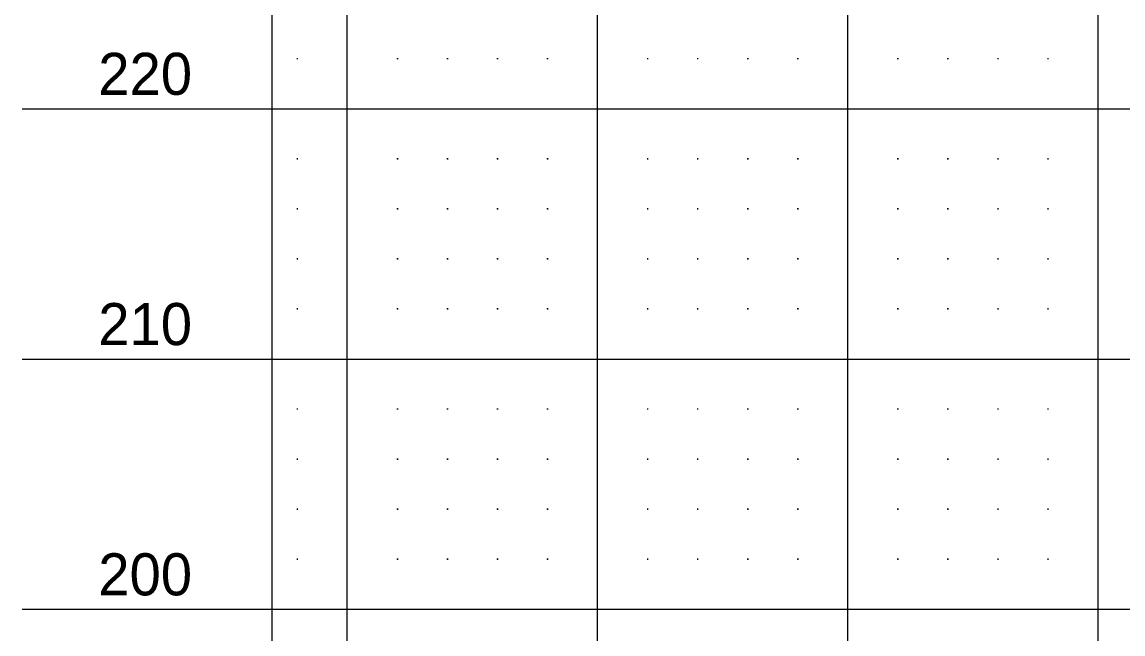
# Model space of a CAD drawing. Extents: x 471 to 2121, y 140 to 650.
# Drawn here: x 471.1 to 691, y 395.1 to 517.3 of the extents above; entities that cross this region are included whole.
import ezdxf

# ---------------------------------------------------------------- set-up
doc = ezdxf.new("R2010")
doc.units = 0
doc.layers.add('DSN_DRFT_Border Grid', color=7, linetype='Continuous')
doc.layers.add('DSN_RDWY_Prof Annotation', color=7, linetype='Continuous')

msp = doc.modelspace()

# ---------------------------------------------------------------- linework, layer by layer
at = {"layer": 'DSN_DRFT_Border Grid'}
for p, q in [((521.06, 150), (521.06, 650)), ((521.06, 150), (521.06, 650)), ((536.06, 150), (536.06, 650)), ((536.06, 150), (536.06, 650)), ((586.06, 150), (586.06, 650)), ((586.06, 150), (586.06, 650)), ((636.06, 150), (636.06, 650)), ((636.06, 150), (636.06, 650)), ((686.06, 150), (686.06, 650)), ((686.06, 150), (686.06, 650)), ((526.18, 510), (525.94, 510)), ((526.18, 510), (525.94, 510)), ((526.06, 510.12), (526.06, 509.88)), ((526.06, 510.12), (526.06, 509.88)), ((546.18, 510), (545.94, 510)), ((546.18, 510), (545.94, 510)), ((546.06, 510.12), (546.06, 509.88)), ((546.06, 510.12), (546.06, 509.88)), ((556.18, 510), (555.94, 510)), ((556.18, 510), (555.94, 510)), ((556.06, 510.12), (556.06, 509.88)), ((556.06, 510.12), (556.06, 509.88)), ((566.18, 510), (565.94, 510)), ((566.18, 510), (565.94, 510)), ((566.06, 510.12), (566.06, 509.88)), ((566.06, 510.12), (566.06, 509.88)), ((576.18, 510), (575.94, 510)), ((576.18, 510), (575.94, 510)), ((576.06, 510.12), (576.06, 509.88)), ((576.06, 510.12), (576.06, 509.88)), ((596.18, 510), (595.94, 510)), ((596.18, 510), (595.94, 510)), ((596.06, 510.12), (596.06, 509.88)), ((596.06, 510.12), (596.06, 509.88)), ((606.18, 510), (605.94, 510)), ((606.18, 510), (605.94, 510)), ((606.06, 510.12), (606.06, 509.88)), ((606.06, 510.12), (606.06, 509.88)), ((616.18, 510), (615.94, 510)), ((616.18, 510), (615.94, 510)), ((616.06, 510.12), (616.06, 509.88)), ((616.06, 510.12), (616.06, 509.88)), ((626.18, 510), (625.94, 510)), ((626.18, 510), (625.94, 510)), ((626.06, 510.12), (626.06, 509.88)), ((626.06, 510.12), (626.06, 509.88)), ((646.18, 510), (645.94, 510)), ((646.18, 510), (645.94, 510)), ((646.06, 510.12), (646.06, 509.88)), ((646.06, 510.12), (646.06, 509.88)), ((656.18, 510), (655.94, 510)), ((656.18, 510), (655.94, 510)), ((656.06, 510.12), (656.06, 509.88)), ((656.06, 510.12), (656.06, 509.88)), ((666.18, 510), (665.94, 510)), ((666.18, 510), (665.94, 510)), ((666.06, 510.12), (666.06, 509.88)), ((666.06, 510.12), (666.06, 509.88)), ((676.18, 510), (675.94, 510)), ((676.18, 510), (675.94, 510)), ((676.06, 510.12), (676.06, 509.88)), ((676.06, 510.12), (676.06, 509.88)), ((471.06, 500), (521.06, 500)), ((521.06, 500), (2071.06, 500)), ((521.06, 500), (2071.06, 500)), ((526.18, 490), (525.94, 490)), ((526.18, 490), (525.94, 490)), ((526.06, 490.12), (526.06, 489.88)), ((526.06, 490.12), (526.06, 489.88)), ((546.18, 490), (545.94, 490)), ((546.18, 490), (545.94, 490)), ((546.06, 490.12), (546.06, 489.88)), ((546.06, 490.12), (546.06, 489.88)), ((556.18, 490), (555.94, 490)), ((556.18, 490), (555.94, 490)), ((556.06, 490.12), (556.06, 489.88)), ((556.06, 490.12), (556.06, 489.88)), ((566.18, 490), (565.94, 490)), ((566.18, 490), (565.94, 490)), ((566.06, 490.12), (566.06, 489.88)), ((566.06, 490.12), (566.06, 489.88)), ((576.18, 490), (575.94, 490)), ((576.18, 490), (575.94, 490)), ((576.06, 490.12), (576.06, 489.88)), ((576.06, 490.12), (576.06, 489.88)), ((596.18, 490), (595.94, 490)), ((596.18, 490), (595.94, 490)), ((596.06, 490.12), (596.06, 489.88)), ((596.06, 490.12), (596.06, 489.88)), ((606.18, 490), (605.94, 490)), ((606.18, 490), (605.94, 490)), ((606.06, 490.12), (606.06, 489.88)), ((606.06, 490.12), (606.06, 489.88)), ((616.18, 490), (615.94, 490)), ((616.18, 490), (615.94, 490)), ((616.06, 490.12), (616.06, 489.88)), ((616.06, 490.12), (616.06, 489.88)), ((626.18, 490), (625.94, 490)), ((626.18, 490), (625.94, 490)), ((626.06, 490.12), (626.06, 489.88)), ((626.06, 490.12), (626.06, 489.88)), ((646.18, 490), (645.94, 490)), ((646.18, 490), (645.94, 490)), ((646.06, 490.12), (646.06, 489.88)), ((646.06, 490.12), (646.06, 489.88)), ((656.18, 490), (655.94, 490)), ((656.18, 490), (655.94, 490)), ((656.06, 490.12), (656.06, 489.88)), ((656.06, 490.12), (656.06, 489.88)), ((666.18, 490), (665.94, 490)), ((666.18, 490), (665.94, 490)), ((666.06, 490.12), (666.06, 489.88)), ((666.06, 490.12), (666.06, 489.88)), ((676.18, 490), (675.94, 490)), ((676.18, 490), (675.94, 490)), ((676.06, 490.12), (676.06, 489.88)), ((676.06, 490.12), (676.06, 489.88)), ((526.18, 480), (525.94, 480)), ((526.18, 480), (525.94, 480)), ((526.06, 480.12), (526.06, 479.88)), ((526.06, 480.12), (526.06, 479.88)), ((546.18, 480), (545.94, 480)), ((546.18, 480), (545.94, 480)), ((546.06, 480.12), (546.06, 479.88)), ((546.06, 480.12), (546.06, 479.88)), ((556.18, 480), (555.94, 480)), ((556.18, 480), (555.94, 480)), ((556.06, 480.12), (556.06, 479.88)), ((556.06, 480.12), (556.06, 479.88)), ((566.18, 480), (565.94, 480)), ((566.18, 480), (565.94, 480)), ((566.06, 480.12), (566.06, 479.88)), ((566.06, 480.12), (566.06, 479.88)), ((576.18, 480), (575.94, 480)), ((576.18, 480), (575.94, 480)), ((576.06, 480.12), (576.06, 479.88)), ((576.06, 480.12), (576.06, 479.88)), ((596.18, 480), (595.94, 480)), ((596.18, 480), (595.94, 480)), ((596.06, 480.12), (596.06, 479.88)), ((596.06, 480.12), (596.06, 479.88)), ((606.18, 480), (605.94, 480)), ((606.18, 480), (605.94, 480)), ((606.06, 480.12), (606.06, 479.88)), ((606.06, 480.12), (606.06, 479.88)), ((616.18, 480), (615.94, 480)), ((616.18, 480), (615.94, 480)), ((616.06, 480.12), (616.06, 479.88)), ((616.06, 480.12), (616.06, 479.88)), ((626.18, 480), (625.94, 480)), ((626.18, 480), (625.94, 480)), ((626.06, 480.12), (626.06, 479.88)), ((626.06, 480.12), (626.06, 479.88)), ((646.18, 480), (645.94, 480)), ((646.18, 480), (645.94, 480)), ((646.06, 480.12), (646.06, 479.88)), ((646.06, 480.12), (646.06, 479.88)), ((656.18, 480), (655.94, 480)), ((656.18, 480), (655.94, 480)), ((656.06, 480.12), (656.06, 479.88)), ((656.06, 480.12), (656.06, 479.88)), ((666.18, 480), (665.94, 480)), ((666.18, 480), (665.94, 480)), ((666.06, 480.12), (666.06, 479.88)), ((666.06, 480.12), (666.06, 479.88)), ((676.18, 480), (675.94, 480)), ((676.18, 480), (675.94, 480)), ((676.06, 480.12), (676.06, 479.88)), ((676.06, 480.12), (676.06, 479.88)), ((526.18, 470), (525.94, 470)), ((526.18, 470), (525.94, 470)), ((526.06, 470.12), (526.06, 469.88)), ((526.06, 470.12), (526.06, 469.88)), ((546.18, 470), (545.94, 470)), ((546.18, 470), (545.94, 470)), ((546.06, 470.12), (546.06, 469.88)), ((546.06, 470.12), (546.06, 469.88)), ((556.18, 470), (555.94, 470)), ((556.18, 470), (555.94, 470)), ((556.06, 470.12), (556.06, 469.88)), ((556.06, 470.12), (556.06, 469.88)), ((566.18, 470), (565.94, 470)), ((566.18, 470), (565.94, 470)), ((566.06, 470.12), (566.06, 469.88)), ((566.06, 470.12), (566.06, 469.88)), ((576.18, 470), (575.94, 470)), ((576.18, 470), (575.94, 470)), ((576.06, 470.12), (576.06, 469.88)), ((576.06, 470.12), (576.06, 469.88)), ((596.18, 470), (595.94, 470)), ((596.18, 470), (595.94, 470)), ((596.06, 470.12), (596.06, 469.88)), ((596.06, 470.12), (596.06, 469.88)), ((606.18, 470), (605.94, 470)), ((606.18, 470), (605.94, 470)), ((606.06, 470.12), (606.06, 469.88)), ((606.06, 470.12), (606.06, 469.88)), ((616.18, 470), (615.94, 470)), ((616.18, 470), (615.94, 470)), ((616.06, 470.12), (616.06, 469.88)), ((616.06, 470.12), (616.06, 469.88)), ((626.18, 470), (625.94, 470)), ((626.18, 470), (625.94, 470)), ((626.06, 470.12), (626.06, 469.88)), ((626.06, 470.12), (626.06, 469.88)), ((646.18, 470), (645.94, 470)), ((646.18, 470), (645.94, 470)), ((646.06, 470.12), (646.06, 469.88)), ((646.06, 470.12), (646.06, 469.88)), ((656.18, 470), (655.94, 470)), ((656.18, 470), (655.94, 470)), ((656.06, 470.12), (656.06, 469.88)), ((656.06, 470.12), (656.06, 469.88)), ((666.18, 470), (665.94, 470)), ((666.18, 470), (665.94, 470)), ((666.06, 470.12), (666.06, 469.88)), ((666.06, 470.12), (666.06, 469.88)), ((676.18, 470), (675.94, 470)), ((676.18, 470), (675.94, 470)), ((676.06, 470.12), (676.06, 469.88)), ((676.06, 470.12), (676.06, 469.88)), ((526.18, 460), (525.94, 460)), ((526.18, 460), (525.94, 460)), ((526.06, 460.12), (526.06, 459.88)), ((526.06, 460.12), (526.06, 459.88)), ((546.18, 460), (545.94, 460)), ((546.18, 460), (545.94, 460)), ((546.06, 460.12), (546.06, 459.88)), ((546.06, 460.12), (546.06, 459.88)), ((556.18, 460), (555.94, 460)), ((556.18, 460), (555.94, 460)), ((556.06, 460.12), (556.06, 459.88)), ((556.06, 460.12), (556.06, 459.88)), ((566.18, 460), (565.94, 460)), ((566.18, 460), (565.94, 460)), ((566.06, 460.12), (566.06, 459.88)), ((566.06, 460.12), (566.06, 459.88)), ((576.18, 460), (575.94, 460)), ((576.18, 460), (575.94, 460)), ((576.06, 460.12), (576.06, 459.88)), ((576.06, 460.12), (576.06, 459.88)), ((596.18, 460), (595.94, 460)), ((596.18, 460), (595.94, 460)), ((596.06, 460.12), (596.06, 459.88)), ((596.06, 460.12), (596.06, 459.88)), ((606.18, 460), (605.94, 460)), ((606.18, 460), (605.94, 460)), ((606.06, 460.12), (606.06, 459.88)), ((606.06, 460.12), (606.06, 459.88)), ((616.18, 460), (615.94, 460)), ((616.18, 460), (615.94, 460)), ((616.06, 460.12), (616.06, 459.88)), ((616.06, 460.12), (616.06, 459.88)), ((626.18, 460), (625.94, 460)), ((626.18, 460), (625.94, 460)), ((626.06, 460.12), (626.06, 459.88)), ((626.06, 460.12), (626.06, 459.88)), ((646.18, 460), (645.94, 460)), ((646.18, 460), (645.94, 460)), ((646.06, 460.12), (646.06, 459.88)), ((646.06, 460.12), (646.06, 459.88)), ((656.18, 460), (655.94, 460)), ((656.18, 460), (655.94, 460)), ((656.06, 460.12), (656.06, 459.88)), ((656.06, 460.12), (656.06, 459.88)), ((666.18, 460), (665.94, 460)), ((666.18, 460), (665.94, 460)), ((666.06, 460.12), (666.06, 459.88)), ((666.06, 460.12), (666.06, 459.88)), ((676.18, 460), (675.94, 460)), ((676.18, 460), (675.94, 460)), ((676.06, 460.12), (676.06, 459.88)), ((676.06, 460.12), (676.06, 459.88)), ((471.06, 450), (521.06, 450)), ((521.06, 450), (2071.06, 450)), ((521.06, 450), (2071.06, 450)), ((526.18, 440), (525.94, 440)), ((526.18, 440), (525.94, 440)), ((526.06, 440.12), (526.06, 439.88)), ((526.06, 440.12), (526.06, 439.88)), ((546.18, 440), (545.94, 440)), ((546.18, 440), (545.94, 440)), ((546.06, 440.12), (546.06, 439.88)), ((546.06, 440.12), (546.06, 439.88)), ((556.18, 440), (555.94, 440)), ((556.18, 440), (555.94, 440)), ((556.06, 440.12), (556.06, 439.88)), ((556.06, 440.12), (556.06, 439.88)), ((566.18, 440), (565.94, 440)), ((566.18, 440), (565.94, 440)), ((566.06, 440.12), (566.06, 439.88)), ((566.06, 440.12), (566.06, 439.88)), ((576.18, 440), (575.94, 440)), ((576.18, 440), (575.94, 440)), ((576.06, 440.12), (576.06, 439.88)), ((576.06, 440.12), (576.06, 439.88)), ((596.18, 440), (595.94, 440)), ((596.18, 440), (595.94, 440)), ((596.06, 440.12), (596.06, 439.88)), ((596.06, 440.12), (596.06, 439.88)), ((606.18, 440), (605.94, 440)), ((606.18, 440), (605.94, 440)), ((606.06, 440.12), (606.06, 439.88)), ((606.06, 440.12), (606.06, 439.88)), ((616.18, 440), (615.94, 440)), ((616.18, 440), (615.94, 440)), ((616.06, 440.12), (616.06, 439.88)), ((616.06, 440.12), (616.06, 439.88)), ((626.18, 440), (625.94, 440)), ((626.18, 440), (625.94, 440)), ((626.06, 440.12), (626.06, 439.88)), ((626.06, 440.12), (626.06, 439.88)), ((646.18, 440), (645.94, 440)), ((646.18, 440), (645.94, 440)), ((646.06, 440.12), (646.06, 439.88)), ((646.06, 440.12), (646.06, 439.88)), ((656.18, 440), (655.94, 440)), ((656.18, 440), (655.94, 440)), ((656.06, 440.12), (656.06, 439.88)), ((656.06, 440.12), (656.06, 439.88)), ((666.18, 440), (665.94, 440)), ((666.18, 440), (665.94, 440)), ((666.06, 440.12), (666.06, 439.88)), ((666.06, 440.12), (666.06, 439.88)), ((676.18, 440), (675.94, 440)), ((676.18, 440), (675.94, 440)), ((676.06, 440.12), (676.06, 439.88)), ((676.06, 440.12), (676.06, 439.88)), ((526.18, 430), (525.94, 430)), ((526.18, 430), (525.94, 430)), ((526.06, 430.12), (526.06, 429.88)), ((526.06, 430.12), (526.06, 429.88)), ((546.18, 430), (545.94, 430)), ((546.18, 430), (545.94, 430)), ((546.06, 430.12), (546.06, 429.88)), ((546.06, 430.12), (546.06, 429.88)), ((556.18, 430), (555.94, 430)), ((556.18, 430), (555.94, 430)), ((556.06, 430.12), (556.06, 429.88)), ((556.06, 430.12), (556.06, 429.88)), ((566.18, 430), (565.94, 430)), ((566.18, 430), (565.94, 430)), ((566.06, 430.12), (566.06, 429.88)), ((566.06, 430.12), (566.06, 429.88)), ((576.18, 430), (575.94, 430)), ((576.18, 430), (575.94, 430)), ((576.06, 430.12), (576.06, 429.88)), ((576.06, 430.12), (576.06, 429.88)), ((596.18, 430), (595.94, 430)), ((596.18, 430), (595.94, 430)), ((596.06, 430.12), (596.06, 429.88)), ((596.06, 430.12), (596.06, 429.88)), ((606.18, 430), (605.94, 430)), ((606.18, 430), (605.94, 430)), ((606.06, 430.12), (606.06, 429.88)), ((606.06, 430.12), (606.06, 429.88)), ((616.18, 430), (615.94, 430)), ((616.18, 430), (615.94, 430)), ((616.06, 430.12), (616.06, 429.88)), ((616.06, 430.12), (616.06, 429.88)), ((626.18, 430), (625.94, 430)), ((626.18, 430), (625.94, 430)), ((626.06, 430.12), (626.06, 429.88)), ((626.06, 430.12), (626.06, 429.88)), ((646.18, 430), (645.94, 430)), ((646.18, 430), (645.94, 430)), ((646.06, 430.12), (646.06, 429.88)), ((646.06, 430.12), (646.06, 429.88)), ((656.18, 430), (655.94, 430)), ((656.18, 430), (655.94, 430)), ((656.06, 430.12), (656.06, 429.88)), ((656.06, 430.12), (656.06, 429.88)), ((666.18, 430), (665.94, 430)), ((666.18, 430), (665.94, 430)), ((666.06, 430.12), (666.06, 429.88)), ((666.06, 430.12), (666.06, 429.88)), ((676.18, 430), (675.94, 430)), ((676.18, 430), (675.94, 430)), ((676.06, 430.12), (676.06, 429.88)), ((676.06, 430.12), (676.06, 429.88)), ((526.18, 420), (525.94, 420)), ((526.18, 420), (525.94, 420)), ((526.06, 420.12), (526.06, 419.88)), ((526.06, 420.12), (526.06, 419.88)), ((546.18, 420), (545.94, 420)), ((546.18, 420), (545.94, 420)), ((546.06, 420.12), (546.06, 419.88)), ((546.06, 420.12), (546.06, 419.88)), ((556.18, 420), (555.94, 420)), ((556.18, 420), (555.94, 420)), ((556.06, 420.12), (556.06, 419.88)), ((556.06, 420.12), (556.06, 419.88)), ((566.18, 420), (565.94, 420)), ((566.18, 420), (565.94, 420)), ((566.06, 420.12), (566.06, 419.88)), ((566.06, 420.12), (566.06, 419.88)), ((576.18, 420), (575.94, 420)), ((576.18, 420), (575.94, 420)), ((576.06, 420.12), (576.06, 419.88)), ((576.06, 420.12), (576.06, 419.88)), ((596.18, 420), (595.94, 420)), ((596.18, 420), (595.94, 420)), ((596.06, 420.12), (596.06, 419.88)), ((596.06, 420.12), (596.06, 419.88)), ((606.18, 420), (605.94, 420)), ((606.18, 420), (605.94, 420)), ((606.06, 420.12), (606.06, 419.88)), ((606.06, 420.12), (606.06, 419.88)), ((616.18, 420), (615.94, 420)), ((616.18, 420), (615.94, 420)), ((616.06, 420.12), (616.06, 419.88)), ((616.06, 420.12), (616.06, 419.88)), ((626.18, 420), (625.94, 420)), ((626.18, 420), (625.94, 420)), ((626.06, 420.12), (626.06, 419.88)), ((626.06, 420.12), (626.06, 419.88)), ((646.18, 420), (645.94, 420)), ((646.18, 420), (645.94, 420)), ((646.06, 420.12), (646.06, 419.88)), ((646.06, 420.12), (646.06, 419.88)), ((656.18, 420), (655.94, 420)), ((656.18, 420), (655.94, 420)), ((656.06, 420.12), (656.06, 419.88)), ((656.06, 420.12), (656.06, 419.88)), ((666.18, 420), (665.94, 420)), ((666.18, 420), (665.94, 420)), ((666.06, 420.12), (666.06, 419.88)), ((666.06, 420.12), (666.06, 419.88)), ((676.18, 420), (675.94, 420)), ((676.18, 420), (675.94, 420)), ((676.06, 420.12), (676.06, 419.88)), ((676.06, 420.12), (676.06, 419.88)), ((526.18, 410), (525.94, 410)), ((526.18, 410), (525.94, 410)), ((526.06, 410.12), (526.06, 409.88)), ((526.06, 410.12), (526.06, 409.88)), ((546.18, 410), (545.94, 410)), ((546.18, 410), (545.94, 410)), ((546.06, 410.12), (546.06, 409.88)), ((546.06, 410.12), (546.06, 409.88)), ((556.18, 410), (555.94, 410)), ((556.18, 410), (555.94, 410)), ((556.06, 410.12), (556.06, 409.88)), ((556.06, 410.12), (556.06, 409.88)), ((566.18, 410), (565.94, 410)), ((566.18, 410), (565.94, 410)), ((566.06, 410.12), (566.06, 409.88)), ((566.06, 410.12), (566.06, 409.88)), ((576.18, 410), (575.94, 410)), ((576.18, 410), (575.94, 410)), ((576.06, 410.12), (576.06, 409.88)), ((576.06, 410.12), (576.06, 409.88)), ((596.18, 410), (595.94, 410)), ((596.18, 410), (595.94, 410)), ((596.06, 410.12), (596.06, 409.88)), ((596.06, 410.12), (596.06, 409.88)), ((606.18, 410), (605.94, 410)), ((606.18, 410), (605.94, 410)), ((606.06, 410.12), (606.06, 409.88)), ((606.06, 410.12), (606.06, 409.88)), ((616.18, 410), (615.94, 410)), ((616.18, 410), (615.94, 410)), ((616.06, 410.12), (616.06, 409.88)), ((616.06, 410.12), (616.06, 409.88)), ((626.18, 410), (625.94, 410)), ((626.18, 410), (625.94, 410)), ((626.06, 410.12), (626.06, 409.88)), ((626.06, 410.12), (626.06, 409.88)), ((646.18, 410), (645.94, 410)), ((646.18, 410), (645.94, 410)), ((646.06, 410.12), (646.06, 409.88)), ((646.06, 410.12), (646.06, 409.88)), ((656.18, 410), (655.94, 410)), ((656.18, 410), (655.94, 410)), ((656.06, 410.12), (656.06, 409.88)), ((656.06, 410.12), (656.06, 409.88)), ((666.18, 410), (665.94, 410)), ((666.18, 410), (665.94, 410)), ((666.06, 410.12), (666.06, 409.88)), ((666.06, 410.12), (666.06, 409.88)), ((676.18, 410), (675.94, 410)), ((676.18, 410), (675.94, 410)), ((676.06, 410.12), (676.06, 409.88)), ((676.06, 410.12), (676.06, 409.88)), ((471.06, 400), (521.06, 400)), ((521.06, 400), (2071.06, 400)), ((521.06, 400), (2071.06, 400))]:
    msp.add_line(p, q, dxfattribs=at)

# ---------------------------------------------------------------- texts
at = {"layer": 'DSN_RDWY_Prof Annotation'}
for s, p in [('220', (486.3, 502.78)), ('220', (486.3, 502.78)), ('210', (486.3, 452.78)), ('210', (486.3, 452.78)), ('200', (486.3, 402.78)), ('200', (486.3, 402.78))]:
    msp.add_text(s, height=8.4, dxfattribs=at).set_placement(p)

doc.saveas('drawing.dxf')
